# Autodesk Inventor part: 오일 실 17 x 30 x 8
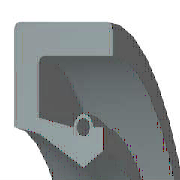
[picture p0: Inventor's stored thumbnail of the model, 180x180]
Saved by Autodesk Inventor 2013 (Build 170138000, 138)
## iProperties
IsCustomPart: 0
Created: 2016-05
Part Number: 오일 실 17 x 30 x 8
Material: 고무
Description: 오일-실
Document SubType Name: Modeling
Standard: KS B 2804
Designer: mduedu
Standards Organization: KS
Language: ko-KR
Size Designation: S - 17 30 8
Categories: <MemberInstance><Categories><Category DisplayName="샤프트 부품" InternalName="7f7aeb1f-a693-4053-b835-cee3144e0d98" Mnemonic="SHFT"><Category DisplayName="실링" Intern
Density: 0.93 g/cm^3
Author: mduedu
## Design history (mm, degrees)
revolve "본체" stored, may be unused: angle "d17" = 90 deg
revolve "스프링1" stored, may be unused: angle "d18" = 90 deg
body "Solid1"
sketch "스케치1"
  geometry: L1 (0, 15)-(8, 15); L2 (8, 15)-(8, 13.75); L3 (8, 13.75)-(1.75, 13.75); L4 (0, 15)-(0, 10.6); L5 (0, 10.6)-(1.75, 10.25); L6 (1.75, 10.25)-(4.9, 8.5); L7 (4.9, 8.5)-(0, 8.5); L8 (6.3, 9.375)-(6.3, 10.6); L9 (0, 0)-(9.586, 0) reference; L10 (4.9, 8.5)-(6.3, 9.375); L11 (0, 18)-(0, -3) reference; L12 (-1.917, 0)-(11.503, 0) reference; L13 (4.2, 10.6)-(1.75, 11.09); L14 (1.75, 11.09)-(1.75, 13.75); L15 (6.3, 10.6)-(5.6, 10.6); C1 r 0.455 at (4.9, 10.6); A1 r 0.7 centre (4.9, 10.6) between (5.6, 10.6) and (4.2, 10.6)
  constraints: 26 end point, 5 horizontal alignment, 4 perpendicular, 2 centre point, 2 collinear, 2 horizontal, 2 parallel, 2 point on circle, 2 point on line, 2 vertical alignment, 1 coincident
  dimensions: "d0" = 30 diameter of L1 L9 (= SD2); "d1" = 18.75 diameter of L8.start L9 (= ABDM); "d2" = 1.25 distance of L1.end L2.end (computed from SD); "d3" = 0.91 diameter of C1 (= SPDI); "d4" = 1.4 diameter of A1 (= SPDA); "d5" = 17 diameter of L6.end L9 (= NND); "d6" = 20.5 diameter of L5.end L9 (= TKDM); "d7" = 21.2 diameter of L4.end L9 (= HLDM); "d8" = 4.9 distance from line of C1.centre L4 (= SPDST); "d9" = 6.3 distance between parallel lines of L8 L4 (= SDI); "d10" = 8 distance between parallel lines of L2 L4 (= SWDT); "d12" = 1.75 distance between parallel lines of L14 L4 (= SD)
fillet "모깎기1" dims "d11" = 0.3 (= RR)
other parameters: "SD2" = 30 [user parameter; used in 1 equation term], "SWDT" = 8 [user parameter; used in 1 equation term], "RR" = 0.3 [user parameter; used in 1 equation term], "SD" = 1.75 [user parameter; used in 2 equation terms], "NND" = 17 [user parameter; used in 1 equation term], "SPDA" = 1.4 [user parameter; used in 1 equation term], "SPDI" = 0.91 [user parameter; used in 1 equation term], "TKDM" = 20.5 [user parameter; used in 1 equation term], "HLDM" = 21.2 [user parameter; used in 1 equation term], "ABDM" = 18.75 [user parameter; used in 1 equation term], "SDI" = 6.3 [user parameter; used in 1 equation term], "SPDST" = 4.9 [user parameter; used in 1 equation term], "d13" = 0, "d14" = 0, "d15" = 0, "LAB" = 0.35 [user parameter]
